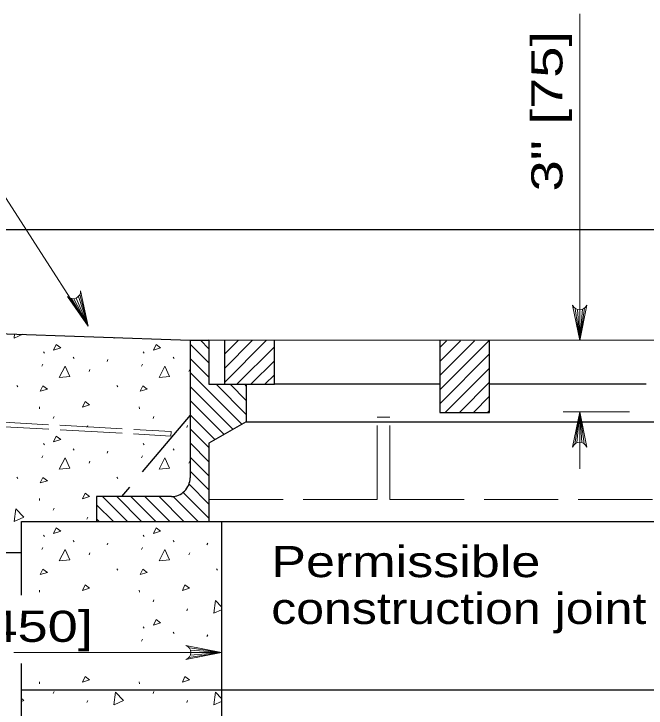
# Model space of a CAD drawing. Extents: x 1083.1 to 1117.1, y 719.4 to 763.4.
# Drawn here: x 1091.157 to 1094.324, y 732.95 to 736.429 of the extents above; entities that cross this region are included whole.
import ezdxf
from ezdxf.enums import TextEntityAlignment as Align

# ---------------------------------------------------------------- set-up
doc = ezdxf.new("R2010")
doc.units = 0
doc.header["$LTSCALE"] = 0.062
doc.linetypes.add('LONG_DASHED', pattern=[7.5, 6, -1.5])
doc.linetypes.add('MEDIUM_DASHED', pattern=[4.5, 3, -1.5])
doc.layers.add('1', color=7, linetype='Continuous', lineweight=13)

msp = doc.modelspace()

# ---------------------------------------------------------------- linework, layer by layer
at = {"layer": '1'}
for p, q in [((1093.99117, 736.42867), (1093.99117, 734.79233)), ((1091.44533, 735.00208), (1091.53008, 734.86417)), ((1091.45775, 735.00158), (1091.53008, 734.86417)), ((1091.46875, 735.00458), (1091.53008, 734.86417)), ((1091.48083, 735.01292), (1091.53008, 734.86417)), ((1091.48792, 735.02275), (1091.53008, 734.86417)), ((1093.96875, 734.95275), (1093.99117, 734.79242)), ((1093.97983, 734.94733), (1093.99117, 734.79242)), ((1094.01592, 734.95458), (1093.99117, 734.79242)), ((1094.00558, 734.9485), (1093.99117, 734.79242)), ((1093.99117, 734.94567), (1093.99117, 734.79242)), ((1091.15808, 734.80342), (1091.16108, 734.82483)), ((1091.2015, 734.82333), (1091.15908, 734.80375)), ((1091.65808, 734.80342), (1091.65858, 734.80683)), ((1091.66525, 734.80658), (1091.65908, 734.80375)), ((1092.13392, 734.75042), (1092.09125, 734.79308)), ((1092.21208, 734.72325), (1092.28192, 734.79308)), ((1092.21208, 734.6525), (1092.35267, 734.79308)), ((1092.21208, 734.58183), (1092.42333, 734.79308)), ((1093.29017, 734.75775), (1093.32367, 734.79125)), ((1093.29017, 734.68708), (1093.39433, 734.79125)), ((1093.29017, 734.61633), (1093.46508, 734.79125)), ((1093.29017, 734.54567), (1093.53575, 734.79125)), ((1092.13392, 734.67967), (1092.04017, 734.77342)), ((1092.2735, 734.5725), (1092.46208, 734.76108)), ((1091.30558, 734.73608), (1091.31008, 734.72942)), ((1091.80558, 734.73608), (1091.81008, 734.72942)), ((1093.29017, 734.475), (1093.54017, 734.72492)), ((1091.45517, 734.70783), (1091.45958, 734.70117)), ((1091.62408, 734.68608), (1091.6285, 734.69608)), ((1091.95517, 734.70783), (1091.95958, 734.70117)), ((1092.13392, 734.60892), (1092.04017, 734.70267)), ((1092.34417, 734.5725), (1092.46208, 734.69042)), ((1091.29725, 734.66292), (1091.30167, 734.67292)), ((1091.53417, 734.63742), (1091.53858, 734.64742)), ((1091.79725, 734.66292), (1091.80167, 734.67292)), ((1092.03417, 734.63742), (1092.03858, 734.64742)), ((1093.31783, 734.432), (1093.54017, 734.65425)), ((1092.29967, 734.37258), (1092.04017, 734.632)), ((1092.41492, 734.5725), (1092.46208, 734.61967)), ((1093.38858, 734.432), (1093.54017, 734.5835)), ((1091.17292, 734.56633), (1091.17733, 734.55967)), ((1091.67292, 734.56633), (1091.67733, 734.55967)), ((1092.25483, 734.34667), (1092.04017, 734.56125)), ((1092.32142, 734.4215), (1092.17033, 734.5725)), ((1092.32142, 734.49225), (1092.24108, 734.5725)), ((1092.32142, 734.56292), (1092.31183, 734.5725)), ((1093.45925, 734.432), (1093.54017, 734.51292)), ((1092.21, 734.32075), (1092.04017, 734.49067)), ((1091.28508, 734.46), (1091.28625, 734.45)), ((1091.78508, 734.46), (1091.78625, 734.45)), ((1093.53, 734.432), (1093.54017, 734.44217)), ((1094.24117, 734.43508), (1093.90783, 734.43508)), ((1093.96633, 734.27283), (1093.99117, 734.43508)), ((1093.97675, 734.279), (1093.99117, 734.43508)), ((1093.99117, 734.14867), (1093.99117, 734.43517)), ((1093.99117, 734.28183), (1093.99117, 734.43508)), ((1094.0025, 734.28017), (1093.99117, 734.43508)), ((1094.01358, 734.27475), (1093.99117, 734.43508)), ((1091.35433, 734.40108), (1091.35875, 734.41108)), ((1091.85433, 734.40108), (1091.85875, 734.41108)), ((1092.16525, 734.29492), (1092.04017, 734.41992)), ((1091.523, 734.3555), (1091.5275, 734.3655)), ((1092.023, 734.3555), (1092.0275, 734.3655)), ((1092.13392, 734.2555), (1092.04017, 734.34925)), ((1091.30558, 734.27675), (1091.31008, 734.27008)), ((1091.80558, 734.27675), (1091.81008, 734.27008)), ((1092.13392, 734.18475), (1092.04017, 734.2785)), ((1091.45517, 734.2485), (1091.45958, 734.24183)), ((1091.62408, 734.22675), (1091.6285, 734.23675)), ((1091.95517, 734.2485), (1091.95958, 734.24183)), ((1091.29725, 734.20358), (1091.30167, 734.21358)), ((1091.79725, 734.20358), (1091.80167, 734.21358)), ((1092.13392, 734.11408), (1092.04017, 734.20783)), ((1091.53417, 734.17808), (1091.53858, 734.18808)), ((1092.03417, 734.17808), (1092.03858, 734.18808)), ((1092.13392, 734.04333), (1092.04017, 734.13708)), ((1091.17292, 734.107), (1091.17733, 734.10033)), ((1091.67292, 734.107), (1091.67733, 734.10033)), ((1092.13392, 733.97275), (1092.03458, 734.072)), ((1092.13392, 733.902), (1092.00508, 734.03075)), ((1091.28508, 734.00058), (1091.28625, 733.99067)), ((1091.7265, 733.88517), (1091.6015, 734.01008)), ((1091.79725, 733.88517), (1091.67225, 734.01008)), ((1091.86792, 733.88517), (1091.74292, 734.01008)), ((1091.93867, 733.88517), (1091.81367, 734.01008)), ((1092.00933, 733.88517), (1091.88433, 734.01008)), ((1092.08008, 733.88517), (1091.95508, 734.01008)), ((1091.35433, 733.94175), (1091.35875, 733.95175)), ((1091.65575, 733.88517), (1091.57142, 733.9695)), ((1091.523, 733.89617), (1091.5275, 733.90617)), ((1091.58508, 733.88517), (1091.57142, 733.89883)), ((1091.58508, 733.88517), (1091.57142, 733.89883)), ((1091.65808, 733.88475), (1091.65817, 733.88517)), ((1091.65925, 733.88517), (1091.65908, 733.88508)), ((1092.15808, 733.88475), (1092.15817, 733.88517)), ((1092.15925, 733.88517), (1092.15908, 733.88508)), ((1091.30558, 733.81742), (1091.31008, 733.81075)), ((1091.80558, 733.81742), (1091.81008, 733.81075)), ((1091.45517, 733.78917), (1091.45958, 733.7825)), ((1091.62408, 733.76742), (1091.6285, 733.77742)), ((1091.95517, 733.78917), (1091.95958, 733.7825)), ((1092.12408, 733.76742), (1092.1285, 733.77742)), ((1091.29725, 733.74425), (1091.30167, 733.75425)), ((1091.79725, 733.74425), (1091.80167, 733.75425)), ((1091.53417, 733.71875), (1091.53858, 733.72875)), ((1092.03417, 733.71875), (1092.03858, 733.72875)), ((1091.67292, 733.64767), (1091.67733, 733.64108)), ((1092.17292, 733.64767), (1092.17733, 733.64108)), ((1091.28508, 733.54125), (1091.28625, 733.53125)), ((1091.78508, 733.54125), (1091.78625, 733.53125)), ((1091.85433, 733.48233), (1091.85875, 733.49233)), ((1092.023, 733.43675), (1092.0275, 733.44675)), ((1092.19642, 733.44292), (1092.15908, 733.42575)), ((1091.80558, 733.35808), (1091.81008, 733.35142)), ((1091.95517, 733.32983), (1091.95958, 733.32317)), ((1091.79725, 733.28492), (1091.80167, 733.29492)), ((1092.12408, 733.30817), (1092.1285, 733.31808)), ((1092.03617, 733.25142), (1092.1965, 733.229)), ((1091.15692, 733.229), (1092.1965, 733.229)), ((1092.03425, 733.20417), (1092.1965, 733.229)), ((1092.04042, 733.21458), (1092.1965, 733.229)), ((1092.04158, 733.24033), (1092.1965, 733.229)), ((1092.04325, 733.229), (1092.1965, 733.229)), ((1091.28508, 733.08192), (1091.28625, 733.07192)), ((1091.78508, 733.08192), (1091.78625, 733.07192)), ((1091.35433, 733.023), (1091.35875, 733.033)), ((1091.85433, 733.023), (1091.85875, 733.033)), ((1091.523, 732.9775), (1091.5275, 732.9875)), ((1092.023, 732.9775), (1092.0275, 732.9875)), ((1092.19642, 732.98358), (1092.15908, 732.96633))]:
    msp.add_line(p, q, dxfattribs=at)
at = {"layer": '1', "lineweight": 25}
for p, q in [((1090.0715, 734.86417), (1092.04017, 734.79308)), ((1092.04017, 734.79308), (1092.04017, 734.10383)), ((1096.72733, 734.79125), (1092.13392, 734.79308)), ((1092.21208, 734.79308), (1092.21208, 734.5725)), ((1093.29017, 734.5725), (1092.46208, 734.5725)), ((1094.3245, 734.5725), (1093.54017, 734.5725)), ((1092.32142, 734.38508), (1096.53983, 734.38508)), ((1091.57142, 734.01008), (1091.57142, 733.88517)), ((1091.94642, 734.01008), (1091.57142, 734.01008)), ((1091.19642, 733.88517), (1097.44608, 733.88517)), ((1091.19642, 733.51575), (1091.19642, 733.88517)), ((1092.19642, 733.88517), (1092.19642, 730.80742))]:
    msp.add_line(p, q, dxfattribs=at)
at = {"layer": '1', "linetype": 'LONG_DASHED', "lineweight": 25}
msp.add_line((1092.04017, 734.41817), (1091.69642, 734.01008), dxfattribs=at)
at = {"layer": '1', "linetype": 'LONG_DASHED'}
for p, q in [((1092.97758, 733.99458), (1092.97758, 734.40858)), ((1092.97758, 734.40858), (1093.04008, 734.40858)), ((1093.04008, 733.99458), (1093.04008, 734.40858)), ((1091.33125, 734.37033), (1091.01917, 734.38767)), ((1091.33275, 734.34742), (1091.02067, 734.36475)), ((1091.69908, 734.34992), (1091.387, 734.36725)), ((1091.7005, 734.327), (1091.3885, 734.34433)), ((1091.94467, 734.33633), (1091.7575, 734.34675)), ((1091.94342, 734.31342), (1091.75625, 734.32383)), ((1092.13392, 733.99458), (1092.97758, 733.99458)), ((1093.04008, 733.99458), (1094.41508, 733.99458))]:
    msp.add_line(p, q, dxfattribs=at)
at = {"layer": '1', "linetype": 'MEDIUM_DASHED'}
msp.add_line((1091.94467, 734.33633), (1091.94342, 734.31342), dxfattribs=at)
at = {"layer": '1'}
for points in [[(1091.53008, 734.86417), (1090.6915, 736.16683), (1090.40142, 736.16683)], [(1091.49167, 735.04058), (1091.53008, 734.86417), (1091.42675, 735.01225)], [(1094.02658, 734.9695), (1093.99117, 734.79242), (1093.95575, 734.9695)], [(1091.38425, 734.60742), (1091.41425, 734.664), (1091.43758, 734.61192), (1091.38542, 734.60742)], [(1091.88425, 734.60742), (1091.91425, 734.664), (1091.93758, 734.61192), (1091.88542, 734.60742)], [(1093.95575, 734.258), (1093.99117, 734.43508), (1094.02658, 734.258)], [(1091.38425, 734.14808), (1091.41425, 734.20467), (1091.43758, 734.15258), (1091.38542, 734.14808)], [(1091.88425, 734.14808), (1091.91425, 734.20467), (1091.93758, 734.15258), (1091.88542, 734.14808)], [(1091.15808, 733.88475), (1091.16692, 733.94817), (1091.20667, 733.90708), (1091.15908, 733.88508)], [(1091.38425, 733.68875), (1091.41425, 733.74542), (1091.43758, 733.69325), (1091.38542, 733.68875)], [(1091.88425, 733.68875), (1091.91425, 733.74542), (1091.93758, 733.69325), (1091.88542, 733.68875)], [(1092.15808, 733.42542), (1092.16692, 733.48875), (1092.19642, 733.45825)], [(1092.01942, 733.19358), (1092.1965, 733.229), (1092.01942, 733.26442)], [(1091.65808, 732.966), (1091.66692, 733.02942), (1091.70667, 732.98833), (1091.65908, 732.96633)], [(1092.15808, 732.966), (1092.16692, 733.02942), (1092.19642, 732.99892)], [(1091.19642, 732.99892), (1091.20667, 732.98833), (1091.19642, 732.98358)]]:
    msp.add_lwpolyline(points, dxfattribs=at)
at = {"layer": '1', "lineweight": 25}
for points in [[(1091.19642, 733.72892), (1090.0715, 733.72892), (1090.0715, 735.34842)], [(1090.0715, 735.34842), (1091.29683, 735.34842), (1093.0845, 735.34842), (1094.87617, 735.34842), (1097.69617, 735.34842)], [(1092.04017, 734.79308), (1092.13392, 734.79308), (1092.13392, 734.5725), (1092.32142, 734.5725), (1092.32142, 734.38508), (1092.13392, 734.27683), (1092.13392, 733.88517)], [(1092.21208, 734.5725), (1092.46208, 734.5725), (1092.46208, 734.79308)], [(1093.29017, 734.79125), (1093.29017, 734.432), (1093.54017, 734.432), (1093.54017, 734.79125)], [(1091.19642, 728.74525), (1091.19642, 730.094), (1091.19642, 733.17367)], [(1091.19642, 733.0415), (1092.27317, 733.0415), (1097.44608, 733.0415)]]:
    msp.add_lwpolyline(points, dxfattribs=at)
at = {"layer": '1'}
for points in [[(1091.3565, 734.74383), (1091.36983, 734.77158), (1091.39208, 734.75492)], [(1091.8565, 734.74383), (1091.86983, 734.77158), (1091.89208, 734.75492)], [(1091.28942, 734.5375), (1091.30275, 734.56525), (1091.325, 734.54858)], [(1091.78942, 734.5375), (1091.80275, 734.56525), (1091.825, 734.54858)], [(1091.50108, 734.45825), (1091.51442, 734.486), (1091.53658, 734.46933)], [(1091.3565, 734.2845), (1091.36983, 734.31225), (1091.39208, 734.29558)], [(1091.28942, 734.07817), (1091.30275, 734.10592), (1091.325, 734.08925)], [(1091.50108, 733.99883), (1091.51442, 734.02658), (1091.53658, 734.00992)], [(1091.3565, 733.82517), (1091.36983, 733.85292), (1091.39208, 733.83625)], [(1091.8565, 733.82517), (1091.86983, 733.85292), (1091.89208, 733.83625)], [(1091.28942, 733.61883), (1091.30275, 733.64658), (1091.325, 733.62992)], [(1091.78942, 733.61883), (1091.80275, 733.64658), (1091.825, 733.62992)], [(1091.50108, 733.5395), (1091.51442, 733.56725), (1091.53658, 733.55058)], [(1092.00108, 733.5395), (1092.01442, 733.56725), (1092.03658, 733.55058)], [(1091.8565, 733.36583), (1091.86983, 733.39358), (1091.89208, 733.37692)], [(1091.50108, 733.08017), (1091.51442, 733.10792), (1091.53658, 733.09125)], [(1092.00108, 733.08017), (1092.01442, 733.10792), (1092.03658, 733.09125)]]:
    msp.add_lwpolyline(points, close=True, dxfattribs=at)
for centre, start, end in [((1091.45346, 735.03952), 225.68232, 1.50845), ((1093.99111, 734.98379), 202.08782, 337.91395), ((1093.99119, 734.24368), 22.08782, 157.91395), ((1092.0051, 733.22903), 292.08605, 67.91218)]:
    msp.add_arc(centre, 0.03822, start, end, dxfattribs=at)
at = {"layer": '1', "lineweight": 25}
msp.add_ellipse((1091.94641, 734.10386), major_axis=(-0.09375, 0), ratio=0.999895, start_param=1.5707963, end_param=3.1415927, dxfattribs=at)

# ---------------------------------------------------------------- texts
at = {"layer": '1', "width": 1.35}
msp.add_text('3" [75]', height=0.156, rotation=90, dxfattribs=at).set_placement((1093.90475, 735.94121), align=Align.CENTER)
at = {"layer": '1'}
for s, width, p in [('Permissible', 1.25, (1092.44633, 733.60633)), ('construction joint', 1.2, (1092.44633, 733.37167))]:
    msp.add_text(s, height=0.156, dxfattribs=dict(at, width=width)).set_placement(p)
at = {"layer": '1', "width": 1.3}
msp.add_text('18" [450]', height=0.156, dxfattribs=at).set_placement((1091.01463, 733.28192), align=Align.CENTER)

doc.saveas('drawing.dxf')
